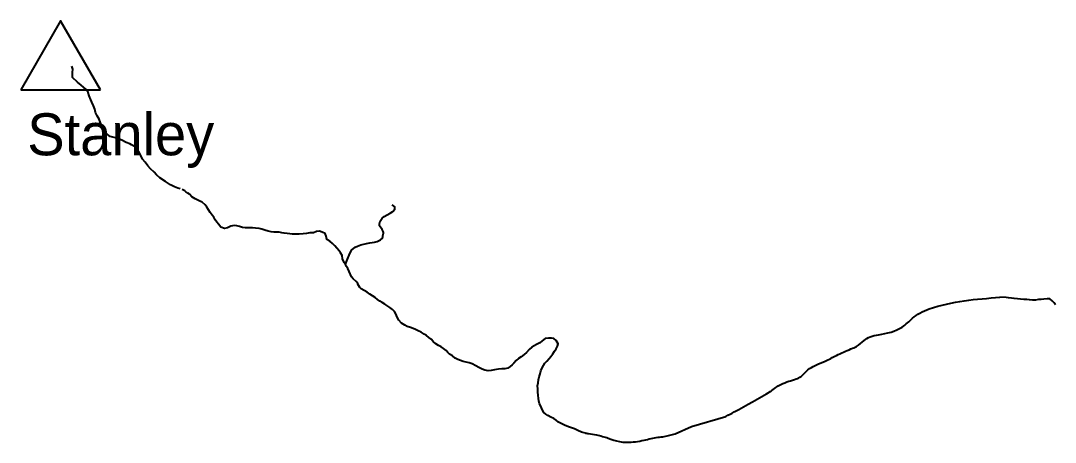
# Model space of a CAD drawing. Extents: x 322505 to 642419, y 5806860 to 5919753.
# Drawn here: x 585646 to 594284, y 5874397 to 5877914 of the extents above; entities that cross this region are included whole.
import ezdxf

# ---------------------------------------------------------------- set-up
doc = ezdxf.new("R2010")
doc.units = 0
doc.header["$LTSCALE"] = 140
doc.layers.add('2', color=7, linetype='Continuous', lineweight=40)
doc.layers.add('4', color=7, linetype='Continuous', lineweight=40)

msp = doc.modelspace()

# ---------------------------------------------------------------- linework, layer by layer
at = {"layer": '2'}
msp.add_line((585646.3, 5877337.4), (586311.6, 5877337.4), dxfattribs=at)
msp.add_lwpolyline([(586311.6, 5877337.4), (585978.9, 5877913.6), (585646.3, 5877337.4)], dxfattribs=at)
at = {"layer": '4'}
for points in [[(586170.4, 5877358), (586150, 5877376.5), (586120.8, 5877401.8), (586080, 5877438.7), (586078.1, 5877481.2), (586080.9, 5877509.6), (586073.1, 5877535.5)], [(586977.7, 5876511.5), (586958.2, 5876517.3), (586929.1, 5876528), (586896, 5876544.5), (586871.7, 5876561), (586856.1, 5876572.7), (586806.6, 5876602.8), (586780.3, 5876629.1), (586760.5, 5876649.3), (586731.3, 5876677), (586707.1, 5876703.2), (586685, 5876732.5), (586663.4, 5876759.7), (586647.9, 5876789.1), (586635, 5876814.9), (586620.6, 5876836.6), (586595.6, 5876863.3), (586571.7, 5876878.4), (586557.2, 5876887.1), (586528, 5876898.8), (586491, 5876917.2), (586453.1, 5876931.8), (586437.6, 5876937.7), (586392.8, 5876947.4), (586357.8, 5876974.6), (586329.6, 5877025.1), (586312.1, 5877062.1), (586302.7, 5877091.9), (586286.1, 5877119.7), (586271.7, 5877148), (586264.8, 5877175.4), (586254.9, 5877202.3), (586239.4, 5877234.1), (586231.6, 5877254.4), (586218.1, 5877288.3), (586208.7, 5877314.1), (586193.8, 5877338.6), (586170.4, 5877358)], [(588852.1, 5875374.5), (588826.6, 5875390), (588804.5, 5875415.2), (588788, 5875439.5), (588788, 5875439.5), (588779.1, 5875468.9), (588766.7, 5875488.6), (588750.3, 5875504.7), (588728.8, 5875520.3), (588710.4, 5875532.8), (588685.4, 5875549.3), (588663.4, 5875563.4), (588644, 5875575.4), (588625.6, 5875587.9), (588606.1, 5875603.5), (588583.4, 5875617.3), (588560.8, 5875633), (588539, 5875647.8), (588514.7, 5875662.6), (588489.6, 5875677.2), (588477.2, 5875689.3), (588462, 5875717.1), (588459.9, 5875722.5), (588447.2, 5875737.7), (588421.2, 5875759.9), (588409.3, 5875777.6), (588389.1, 5875822.1), (588377.2, 5875846.8), (588366.5, 5875862.4), (588357.4, 5875881.3), (588346.7, 5875897), (588333.9, 5875927.3), (588330.6, 5875953.7), (588330.6, 5875953.7), (588317.2, 5875977), (588305.3, 5875993.6), (588285.8, 5876016.8), (588269.9, 5876034.5), (588249.4, 5876054.6), (588226.8, 5876073.7), (588202.3, 5876088.3), (588202.3, 5876088.3), (588197, 5876117.2), (588188.7, 5876138.4), (588188.7, 5876138.4), (588163.1, 5876150.4), (588141.2, 5876157.3), (588116.3, 5876154.1), (588089.5, 5876144.7), (588061, 5876142.9), (588033.1, 5876138.6), (588003.2, 5876136.3), (587971.7, 5876133), (587942.2, 5876132.7), (587915.3, 5876134), (587893.4, 5876136.9), (587870, 5876138.2), (587846.1, 5876141), (587825.7, 5876145.4), (587805.3, 5876148.8), (587782.5, 5876149.6), (587758.6, 5876151), (587736.7, 5876153.3), (587711.2, 5876157.7), (587685.2, 5876165.6), (587659.8, 5876174), (587636.3, 5876180.4), (587607.3, 5876183.2), (587581.4, 5876185.5), (587550.9, 5876186.7), (587522.4, 5876186.5), (587497.5, 5876189.8), (587472, 5876196.2), (587449.6, 5876203.1), (587427.2, 5876206), (587400.3, 5876199.7), (587373.5, 5876185.2), (587373.5, 5876185.2), (587349.1, 5876181.4), (587349.1, 5876181.4), (587316, 5876190.3), (587316, 5876190.3), (587297.5, 5876216), (587285.1, 5876234.2), (587271.2, 5876253.4), (587257.8, 5876274.6), (587244.5, 5876290.3), (587229, 5876313), (587215.1, 5876337.3), (587199.7, 5876357.9), (587185.3, 5876377.1), (587160, 5876399.5), (587142.5, 5876408.2), (587126, 5876416), (587102.6, 5876426.7), (587076.4, 5876443.2), (587055.5, 5876465.8), (587040.9, 5876475.5), (587026.3, 5876486.2), (587016.6, 5876494.9), (586993.2, 5876504.7)], [(588357.8, 5875881.3), (588363.7, 5875897.4), (588381.2, 5875938), (588383.1, 5875944.8), (588388, 5875958.4), (588400.6, 5875982.7), (588411.3, 5876002.2), (588422, 5876011.9), (588439.5, 5876023.6), (588459, 5876032.3), (588485.2, 5876044), (588533.8, 5876054.7), (588562, 5876061.5), (588599, 5876066.3), (588621.3, 5876071.2), (588649.5, 5876084.8), (588666.1, 5876099.4), (588670, 5876113.9), (588670, 5876119.8), (588675.8, 5876140.2), (588673.9, 5876146), (588671.9, 5876154.8), (588663.2, 5876173.2), (588642.7, 5876201.4), (588640.8, 5876220.1), (588648.6, 5876242.2), (588664.1, 5876267.5), (588681.3, 5876280.5), (588705.7, 5876295.4), (588730.5, 5876306.8), (588753.7, 5876323.2), (588769.3, 5876342.2), (588770.1, 5876359.8), (588769.1, 5876360.8), (588748.7, 5876377.3)], [(594286, 5875542.8), (594275.2, 5875560.5), (594256.2, 5875577.1), (594238.8, 5875592.7), (594238.8, 5875592.7), (594215.4, 5875593.5), (594189, 5875591.8), (594166.7, 5875589), (594142.3, 5875587.8), (594119.4, 5875583), (594094, 5875582.3), (594068.1, 5875584.1), (594046.2, 5875589), (594021.3, 5875588.8), (593994.3, 5875590.1), (593968.4, 5875592.4), (593941.4, 5875595.7), (593917, 5875599), (593894.1, 5875601.9), (593872.2, 5875604.8), (593821.7, 5875606.1)], [(590360.3, 5874474), (590328.4, 5874482), (590328.4, 5874482), (590297.8, 5874494.4), (590270.3, 5874507.9), (590245.3, 5874517.3), (590219.3, 5874525.2), (590185.1, 5874539.2), (590158, 5874552.6), (590136.1, 5874563.6), (590116.6, 5874580.2), (590097.7, 5874594.3), (590071.2, 5874605.2), (590046.6, 5874619.3), (590029.3, 5874631.8), (590014.4, 5874646.4), (589999.4, 5874671.7), (589988, 5874697.5), (589978.7, 5874718.2), (589971.4, 5874742.1), (589969.6, 5874762.4), (589965.3, 5874789.8), (589963.6, 5874813.6), (589962.3, 5874843.1), (589962.1, 5874866.5), (589965.4, 5874893.4), (589969.8, 5874917.3), (589975.7, 5874943.3), (589982, 5874968.8), (589990, 5874992.2), (589997.9, 5875013.6), (590010.4, 5875036.1), (590022.4, 5875055.5), (590038.5, 5875074.9), (590057.2, 5875095.4), (590071.8, 5875111.3), (590089.9, 5875133.8), (590103.9, 5875155.8), (590116.9, 5875176.2), (590128.4, 5875197.6), (590132.8, 5875218.5), (590132.8, 5875218.5), (590115.3, 5875247.3), (590097.9, 5875262.9), (590077, 5875265.8), (590053.6, 5875266.1), (590025.2, 5875261.8), (589998.4, 5875243.3), (589979.2, 5875227.3), (589953.4, 5875213.9), (589933.2, 5875202.5), (589913.5, 5875191.7), (589913.5, 5875191.7), (589892.3, 5875170.7), (589869.2, 5875145.6), (589850.5, 5875129.7), (589825.8, 5875110.7), (589802.5, 5875094.7), (589783.3, 5875079.3), (589763.7, 5875057.3), (589749.1, 5875041.9), (589732.5, 5875028.1), (589713.3, 5875014.7), (589713.3, 5875014.7), (589687.9, 5875010.9), (589664, 5875009.7), (589634.6, 5875006.4), (589602.1, 5875001.5), (589575.2, 5874995.7), (589548.8, 5874993.4), (589522.3, 5874998.3), (589497.8, 5875006.7), (589471.3, 5875020.2), (589445.8, 5875033.7), (589416.6, 5875050.2), (589389.6, 5875060.1), (589365.2, 5875066), (589340.2, 5875071.9), (589318.8, 5875077.8), (589296.9, 5875087.3), (589273.4, 5875099.8), (589250.4, 5875116.8), (589227.3, 5875132.4), (589211, 5875146.5), (589198.1, 5875162.6), (589176.1, 5875180.2), (589156.7, 5875192.7), (589133.2, 5875204.2), (589111.2, 5875218.7), (589090.7, 5875237.4), (589073.3, 5875256.5), (589054.8, 5875270.6), (589035.4, 5875287.2), (589015.9, 5875299.7), (588989.4, 5875314.7), (588963.9, 5875326.2), (588941.4, 5875336.7), (588921.5, 5875346.1), (588899.6, 5875354.1), (588872, 5875363), (588852.1, 5875374.5)], [(591110.4, 5874468.3), (591247.2, 5874527.5), (591532.6, 5874612.5)]]:
    msp.add_lwpolyline(points, dxfattribs=at)
for points in [[(592577.5, 5875176.1), (592624.1, 5875196.5), (592687.4, 5875246.3), (592737.2, 5875277.1), (592808.4, 5875294.5), (593006.1, 5875357.8), (593092.3, 5875431.3), (593152.4, 5875474.8), (593230.7, 5875508.8), (593523.3, 5875577.5), (593821.7, 5875606.1)], [(591908.4, 5874821.7), (591992.2, 5874879.4), (592058.6, 5874905.5), (592121.1, 5874925.3), (592160.6, 5874945.8), (592217.6, 5875000.4), (592280.1, 5875038.3), (592362.3, 5875073.9), (592455.6, 5875120.6), (592577.5, 5875176.1)], [(591532.6, 5874612.5), (591603.1, 5874650.2), (591909.5, 5874822.4)], [(590360.3, 5874474), (590387.5, 5874469.9), (590452.4, 5874458), (590551.2, 5874431.9), (590644.6, 5874402.7), (590704.7, 5874397.2), (590850.2, 5874414.5), (590967.2, 5874439.1), (591019.4, 5874445.4), (591110.4, 5874468.3)]]:
    msp.add_spline(points, degree=3, dxfattribs=at)

# ---------------------------------------------------------------- texts
at = {"layer": '2'}
msp.add_text('Stanley', height=350, dxfattribs=at).set_placement((585700.9, 5876791))

doc.saveas('drawing.dxf')
